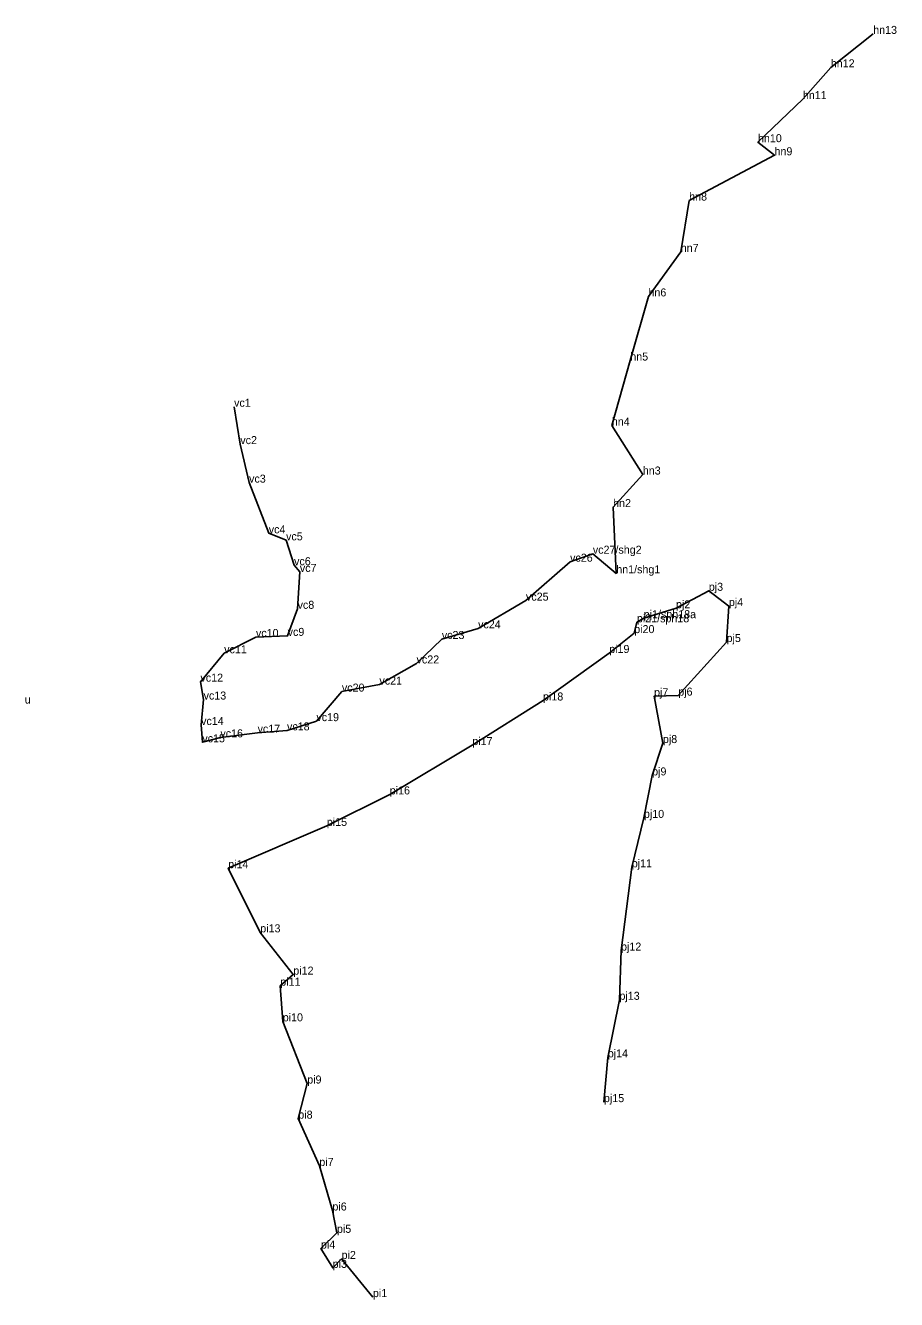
# Model space of a CAD drawing. Extents: x 2072529 to 2267990, y 436423 to 470008.
# Drawn here: x 2168637 to 2169182, y 443372 to 444168 of the extents above; entities that cross this region are included whole.
import ezdxf

# ---------------------------------------------------------------- set-up
doc = ezdxf.new("R2010")
doc.units = 0
doc.layers.add('Level 3', color=7, linetype='Continuous')
doc.layers.add('Old_Level_52', color=7, linetype='Continuous')

msp = doc.modelspace()

# ---------------------------------------------------------------- linework, layer by layer
at = {"layer": 'Level 3'}
for p, q in [((2169167.13, 444163.002), (2169167.13, 444163.002)), ((2169140.631, 444142.118), (2169140.631, 444142.118)), ((2169123.163, 444122.299), (2169123.163, 444122.299)), ((2169095.078, 444095.359), (2169095.078, 444095.359)), ((2169105.433, 444087.164), (2169105.433, 444087.164)), ((2169052.058, 444058.873), (2169052.058, 444058.873)), ((2169046.828, 444026.811), (2169046.828, 444026.811)), ((2169026.616, 443998.975), (2169026.616, 443998.975)), ((2169015.261, 443958.913), (2169015.261, 443958.913)), ((2168767.567, 443930.064), (2168767.567, 443930.064)), ((2169003.727, 443918.332), (2169003.727, 443918.332)), ((2168771.46, 443906.709), (2168771.46, 443906.709)), ((2169023.095, 443887.704), (2169023.095, 443887.704)), ((2168776.951, 443882.658), (2168776.951, 443882.658)), ((2169004.523, 443867.368), (2169004.523, 443867.368)), ((2168789.244, 443850.977), (2168789.244, 443850.977)), ((2168800.063, 443846.596), (2168800.063, 443846.596)), ((2168991.858, 443838.24), (2168991.858, 443838.24)), ((2168805.077, 443831.043), (2168805.077, 443831.043)), ((2168977.633, 443833.242), (2168977.633, 443833.242)), ((2168808.703, 443826.843), (2168808.703, 443826.843)), ((2169006.5, 443825.972), (2169006.5, 443825.972)), ((2169064.343, 443815.067), (2169064.343, 443815.067)), ((2168807.274, 443803.808), (2168807.274, 443803.808)), ((2168950.06, 443808.914), (2168950.06, 443808.914)), ((2169043.851, 443804.126), (2169043.851, 443804.126)), ((2169076.888, 443805.52), (2169076.888, 443805.52)), ((2169023.653, 443797.942), (2169023.653, 443797.942)), ((2168920.131, 443791.606), (2168920.131, 443791.606)), ((2169017.71, 443788.625), (2169017.71, 443788.625)), ((2169019.388, 443795.394), (2169019.388, 443795.394)), ((2168781.247, 443786.191), (2168781.247, 443786.191)), ((2168801.057, 443786.902), (2168801.057, 443786.902)), ((2168897.446, 443784.943), (2168897.446, 443784.943)), ((2169075.444, 443783.051), (2169075.444, 443783.051)), ((2168761.379, 443776.024), (2168761.379, 443776.024)), ((2169002.074, 443776.201), (2169002.074, 443776.201)), ((2168881.668, 443769.671), (2168881.668, 443769.671)), ((2168746.544, 443758.291), (2168746.544, 443758.291)), ((2168858.428, 443756.451), (2168858.428, 443756.451)), ((2168834.967, 443752.093), (2168834.967, 443752.093)), ((2169030.138, 443749.203), (2169030.138, 443749.203)), ((2169045.248, 443749.584), (2169045.248, 443749.584)), ((2168748.518, 443747.119), (2168748.518, 443747.119)), ((2168960.716, 443746.529), (2168960.716, 443746.529)), ((2168819.042, 443733.626), (2168819.042, 443733.626)), ((2168746.95, 443731.237), (2168746.95, 443731.237)), ((2168782.265, 443726.397), (2168782.265, 443726.397)), ((2168800.664, 443727.866), (2168800.664, 443727.866)), ((2168747.726, 443720.392), (2168747.726, 443720.392)), ((2168759.006, 443723.502), (2168759.006, 443723.502)), ((2168916.491, 443718.663), (2168916.491, 443718.663)), ((2169035.648, 443719.925), (2169035.648, 443719.925)), ((2169028.927, 443699.717), (2169028.927, 443699.717)), ((2168864.889, 443687.854), (2168864.889, 443687.854)), ((2169023.777, 443673.186), (2169023.777, 443673.186)), ((2168825.549, 443668.145), (2168825.549, 443668.145)), ((2168763.894, 443641.732), (2168763.894, 443641.732)), ((2169016.206, 443642.306), (2169016.206, 443642.306)), ((2168783.926, 443601.662), (2168783.926, 443601.662)), ((2169009.483, 443590.273), (2169009.483, 443590.273)), ((2168804.578, 443575.266), (2168804.578, 443575.266)), ((2168796.443, 443568.326), (2168796.443, 443568.326)), ((2169008.479, 443559.526), (2169008.479, 443559.526)), ((2168797.986, 443546.071), (2168797.986, 443546.071)), ((2169001.198, 443523.575), (2169001.198, 443523.575)), ((2168813.294, 443507.205), (2168813.294, 443507.205)), ((2168998.771, 443495.592), (2168998.771, 443495.592)), ((2168807.72, 443485.262), (2168807.72, 443485.262)), ((2168820.872, 443455.723), (2168820.872, 443455.723)), ((2168829.041, 443427.87), (2168829.041, 443427.87)), ((2168831.893, 443413.929), (2168831.893, 443413.929)), ((2168821.87, 443404.103), (2168821.87, 443404.103)), ((2168829.196, 443392.043), (2168829.196, 443392.043)), ((2168834.77, 443397.614), (2168834.77, 443397.614)), ((2168854.341, 443373.773), (2168854.341, 443373.773))]:
    msp.add_line(p, q, dxfattribs=at)
at = {"layer": 'Old_Level_52'}
for points in [[(2168767.567, 443930.064), (2168771.46, 443906.709), (2168776.951, 443882.658), (2168789.244, 443850.977), (2168800.063, 443846.596), (2168805.077, 443831.043), (2168808.703, 443826.843), (2168807.274, 443803.808), (2168801.057, 443786.902), (2168781.247, 443786.191), (2168761.379, 443776.024), (2168746.544, 443758.291), (2168748.518, 443747.119), (2168746.95, 443731.237), (2168747.726, 443720.392), (2168759.006, 443723.502), (2168782.265, 443726.397), (2168800.664, 443727.866), (2168819.042, 443733.626), (2168834.967, 443752.093), (2168858.428, 443756.451), (2168881.668, 443769.671), (2168897.446, 443784.943), (2168920.131, 443791.606), (2168950.06, 443808.914), (2168977.633, 443833.242), (2168991.858, 443838.24), (2169006.5, 443825.972), (2169004.523, 443867.368), (2169023.095, 443887.704), (2169003.727, 443918.332), (2169015.261, 443958.913), (2169026.616, 443998.975), (2169046.828, 444026.811), (2169052.058, 444058.873), (2169105.433, 444087.164), (2169095.078, 444095.359), (2169123.163, 444122.299), (2169140.631, 444142.118), (2169167.13, 444163.002)], [(2168854.341, 443373.773), (2168834.77, 443397.614), (2168829.196, 443392.043), (2168821.87, 443404.103), (2168831.893, 443413.929), (2168829.041, 443427.87), (2168820.872, 443455.723), (2168807.72, 443485.262), (2168813.294, 443507.205), (2168797.986, 443546.071), (2168796.443, 443568.326), (2168804.578, 443575.266), (2168783.926, 443601.662), (2168763.894, 443641.732), (2168825.549, 443668.145), (2168864.889, 443687.854), (2168916.491, 443718.663), (2168960.716, 443746.529), (2169002.074, 443776.201), (2169017.71, 443788.625), (2169019.388, 443795.394), (2169023.653, 443797.942), (2169043.851, 443804.126), (2169064.343, 443815.067), (2169076.888, 443805.52), (2169075.444, 443783.051), (2169045.248, 443749.584), (2169030.138, 443749.203), (2169035.648, 443719.925), (2169028.927, 443699.717), (2169023.777, 443673.186), (2169016.206, 443642.306), (2169009.483, 443590.273), (2169008.479, 443559.526), (2169001.198, 443523.575), (2168998.771, 443495.592)]]:
    msp.add_lwpolyline(points, dxfattribs=at)

# ---------------------------------------------------------------- texts
for s, p in [('hn13', (2169167.13, 444163.002)), ('hn12', (2169140.631, 444142.118)), ('hn11', (2169123.163, 444122.299)), ('hn10', (2169095.078, 444095.359)), ('hn9', (2169105.433, 444087.164)), ('hn8', (2169052.058, 444058.873)), ('hn7', (2169046.828, 444026.811)), ('hn6', (2169026.616, 443998.975)), ('hn5', (2169015.261, 443958.913)), ('vc1', (2168767.567, 443930.064)), ('hn4', (2169003.727, 443918.332)), ('vc2', (2168771.46, 443906.709)), ('hn3', (2169023.095, 443887.704)), ('vc3', (2168776.951, 443882.658)), ('hn2', (2169004.523, 443867.368)), ('vc4', (2168789.244, 443850.977)), ('vc5', (2168800.063, 443846.596)), ('vc27/shg2', (2168991.858, 443838.24)), ('vc6', (2168805.077, 443831.043)), ('vc26', (2168977.633, 443833.242)), ('vc7', (2168808.703, 443826.843)), ('hn1/shg1', (2169006.5, 443825.972)), ('pj3', (2169064.343, 443815.067)), ('vc25', (2168950.06, 443808.914)), ('vc8', (2168807.274, 443803.808)), ('pj2', (2169043.851, 443804.126)), ('pj4', (2169076.888, 443805.52)), ('vc24', (2168920.131, 443791.606)), ('pi21/sph18', (2169019.388, 443795.394)), ('pj1/sph18a', (2169023.653, 443797.942)), ('vc10', (2168781.247, 443786.191)), ('vc9', (2168801.057, 443786.902)), ('vc23', (2168897.446, 443784.943)), ('pi20', (2169017.71, 443788.625)), ('pj5', (2169075.444, 443783.051)), ('vc11', (2168761.379, 443776.024)), ('pi19', (2169002.074, 443776.201)), ('vc22', (2168881.668, 443769.671)), ('vc12', (2168746.544, 443758.291)), ('vc20', (2168834.967, 443752.093)), ('vc21', (2168858.428, 443756.451)), ('u', (2168636.708, 443744.62)), ('vc13', (2168748.518, 443747.119)), ('pi18', (2168960.716, 443746.529)), ('pj7', (2169030.138, 443749.203)), ('pj6', (2169045.248, 443749.584)), ('vc14', (2168746.95, 443731.237)), ('vc18', (2168800.664, 443727.866)), ('vc19', (2168819.042, 443733.626)), ('vc15', (2168747.726, 443720.392)), ('vc16', (2168759.006, 443723.502)), ('vc17', (2168782.265, 443726.397)), ('pj8', (2169035.648, 443719.925)), ('pi17', (2168916.491, 443718.663)), ('pj9', (2169028.927, 443699.717)), ('pi16', (2168864.889, 443687.854)), ('pj10', (2169023.777, 443673.186)), ('pi15', (2168825.549, 443668.145)), ('pi14', (2168763.894, 443641.732)), ('pj11', (2169016.206, 443642.306)), ('pi13', (2168783.926, 443601.662)), ('pj12', (2169009.483, 443590.273)), ('pi11', (2168796.443, 443568.326)), ('pi12', (2168804.578, 443575.266)), ('pj13', (2169008.479, 443559.526)), ('pi10', (2168797.986, 443546.071)), ('pj14', (2169001.198, 443523.575)), ('pi9', (2168813.294, 443507.205)), ('pj15', (2168998.771, 443495.592)), ('pi8', (2168807.72, 443485.262)), ('pi7', (2168820.872, 443455.723)), ('pi6', (2168829.041, 443427.87)), ('pi5', (2168831.893, 443413.929)), ('pi4', (2168821.87, 443404.103)), ('pi2', (2168834.77, 443397.614)), ('pi3', (2168829.196, 443392.043)), ('pi1', (2168854.341, 443373.773))]:
    msp.add_text(s, height=5).set_placement(p)

doc.saveas('drawing.dxf')
